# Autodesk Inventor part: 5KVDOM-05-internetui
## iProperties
Created: 2010-11
Part Number: 5KVDOM-05-internetui
Document SubType Name: Modeling
Designer: Darius
Author: Darius
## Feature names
1. Base1
